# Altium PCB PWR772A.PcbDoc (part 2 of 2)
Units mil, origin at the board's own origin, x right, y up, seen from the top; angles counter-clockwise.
Board outline 3500 x 3300 mil, 4 copper layers (Top Layer, Signal Layer 1, Signal Layer 2, Bottom Layer), stack 30.2 mil thick; 164 components, 50 nets, 349 pads, 587 vias.
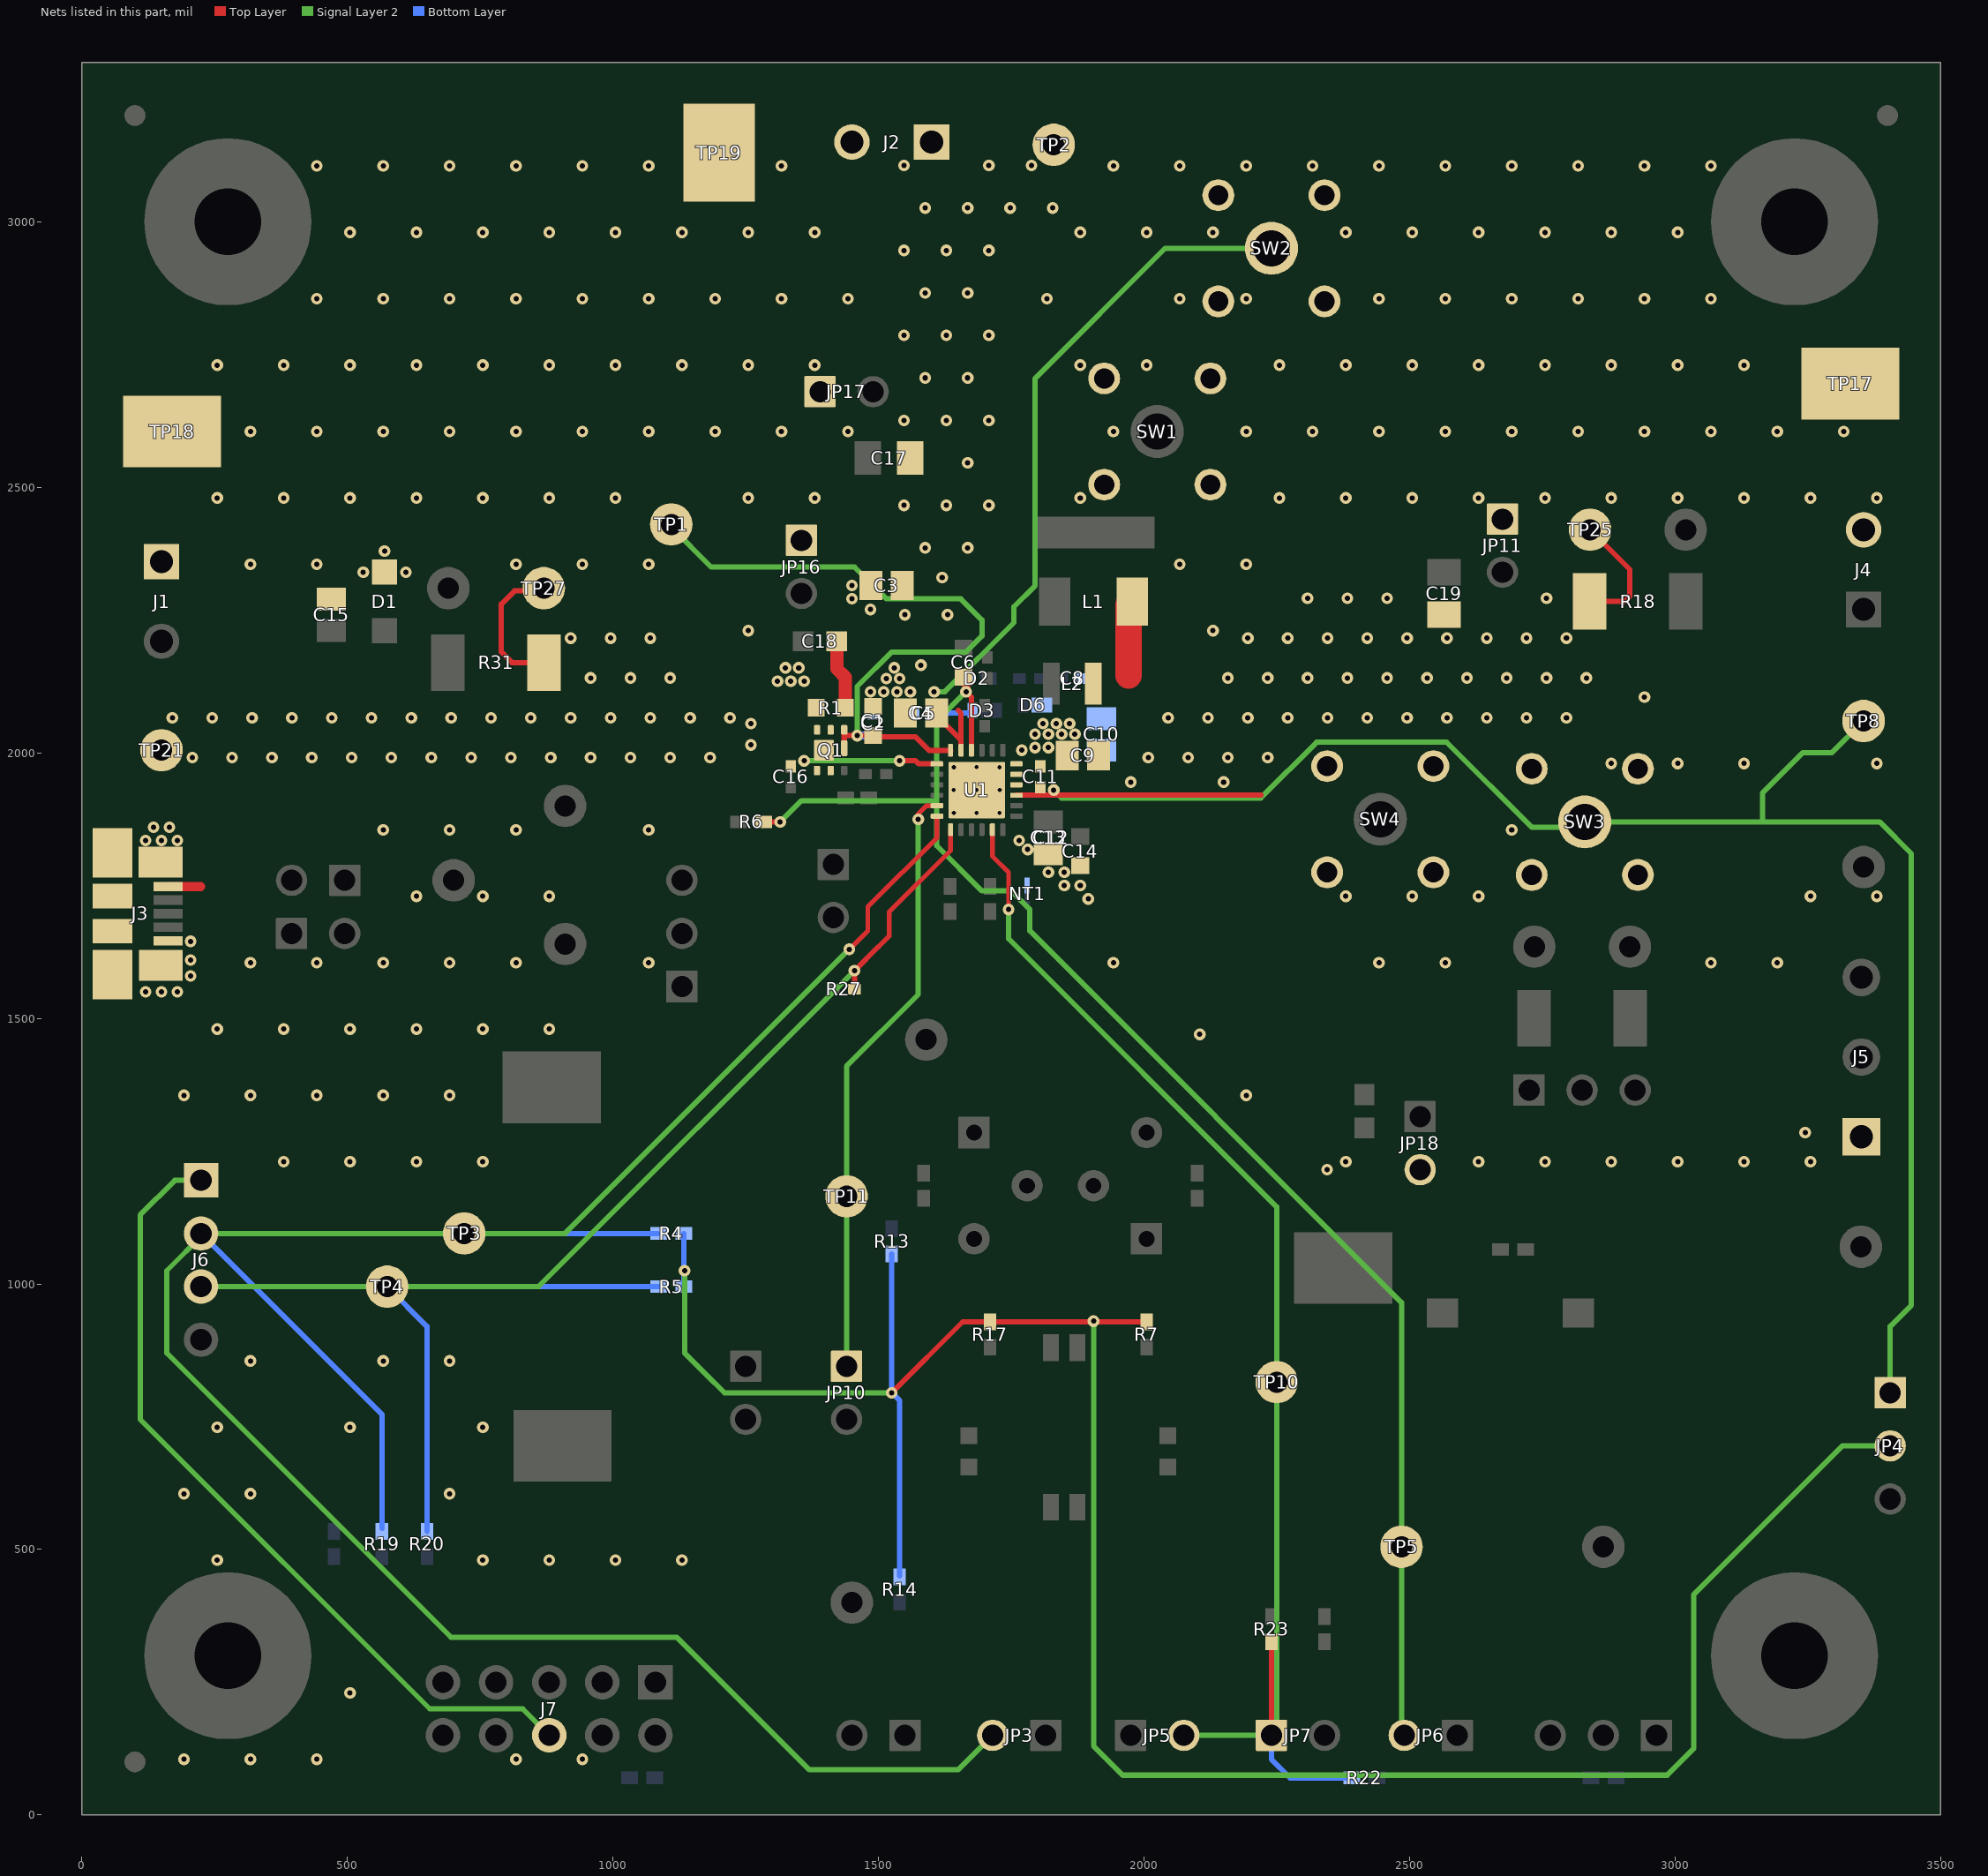
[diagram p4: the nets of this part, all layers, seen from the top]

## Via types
v1: diameter 22, hole 10, Top Layer to Bottom Layer, tented both sides, 573 vias
v2: diameter 19.68, hole 7.87, Top Layer to Bottom Layer, 14 vias

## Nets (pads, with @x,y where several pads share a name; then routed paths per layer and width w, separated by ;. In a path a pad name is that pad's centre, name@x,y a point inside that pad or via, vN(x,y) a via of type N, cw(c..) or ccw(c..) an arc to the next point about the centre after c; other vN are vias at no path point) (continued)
PGND: C1.2 C2.2 C3.2 C4.2 C5.2 C8.2 C9.2 C10.2 C11.2 C12.1 C13.1 C14.1 C15.2 D1.2 D6.2 J1.1 J2.2 J3.5 J3.6 J3.7 J3.8 J3.9 J3.10 J3.11 J4.2 J5.1 J6.1 J7.6 JP11.1 JP16.1 JP17.1 JP18.2 NT1.1 SW1.2 SW1.3 SW1.4 SW1.5 SW2.2 SW2.3 SW2.4 SW2.5 SW3.2 SW3.3 SW3.4 SW3.5 SW4.2 SW4.3 SW4.4 SW4.5 TP17.1 TP18.1 TP19.1 U1.17 U1.18 U1.25@1685,1930 | length 1542.8
  Signal Layer 2 w10: J6.1@224.41,1195 175,1195 110,1130 110,745 655,200 830,200 J7.6@880,150
  other v1: 192.5,105 317.5,105 442.5,105 817.5,105 942.5,105 505,230 255,480 755,480 880,480 1005,480 1130,480 192.5,605 317.5,605 692.5,605 255,730 505,730 755,730 317.5,855 567.5,855 692.5,855 2345,1215 380,1230 505,1230 630,1230 755,1230 2380,1230 2630,1230 2755,1230 2880,1230 3005,1230 3130,1230 3255,1230 3245,1285 192.5,1355 317.5,1355 442.5,1355 567.5,1355 692.5,1355 2192.5,1355 2105,1470 255,1480 380,1480 505,1480 630,1480 755,1480 880,1480 120,1550 150,1550 180,1550 205,1580 317.5,1605 442.5,1605 567.5,1605 692.5,1605 817.5,1605 1067.5,1605 1942.5,1605 2442.5,1605 2567.5,1605 3067.5,1605 3192.5,1605 205,1610 205,1645 1895,1725 630,1730 755,1730 880,1730 2380,1730 2505,1730 2630,1730 3255,1730 3380,1730 1850,1750 1880,1750 1820,1775 1850,1775 1781,1818 120,1835 150,1835 180,1835 1765,1835 567.5,1855 692.5,1855 817.5,1855 1067.5,1855 2692.5,1855 135,1860 165,1860 2880,1980 3005,1980 3130,1980 3380,1980 1770,2005 1795,2010 1820,2010 1795,2035 1820,2035 1845,2035 1870,2035 1810,2055 1835,2055 1860,2055 2942.5,2105 1485,2115 1510,2115 1535,2115 1560,2115 1310,2135 1335,2135 1360,2135 1515,2140 1540,2140 1325,2160 1350,2160 1530,2160 1255,2230 2130,2230 1485,2270 1450,2290 1450,2315 530,2340 610,2340 317.5,2355 442.5,2355 817.5,2355 942.5,2355 1067.5,2355 2067.5,2355 2192.5,2355 570,2380 255,2480 380,2480 505,2480 630,2480 755,2480 880,2480 1005,2480 1255,2480 1380,2480 1880,2480 2255,2480 2380,2480 2505,2480 2630,2480 2755,2480 2880,2480 3005,2480 3130,2480 3255,2480 3380,2480 317.5,2605 442.5,2605 567.5,2605 692.5,2605 817.5,2605 942.5,2605 1067.5,2605 1192.5,2605 1317.5,2605 1442.5,2605 1942.5,2605 2192.5,2605 2317.5,2605 2442.5,2605 2567.5,2605 2692.5,2605 2817.5,2605 2942.5,2605 3067.5,2605 3192.5,2605 3317.5,2605 255,2730 380,2730 505,2730 630,2730 755,2730 880,2730 1005,2730 1130,2730 1255,2730 1380,2730 1880,2730 2005,2730 2255,2730 2380,2730 2505,2730 2630,2730 2755,2730 2880,2730 3005,2730 3130,2730 442.5,2855 567.5,2855 692.5,2855 817.5,2855 942.5,2855 1067.5,2855 1192.5,2855 1317.5,2855 1442.5,2855 1817.5,2855 2067.5,2855 2192.5,2855 2442.5,2855 2567.5,2855 2692.5,2855 2817.5,2855 2942.5,2855 3067.5,2855 505,2980 630,2980 755,2980 880,2980 1005,2980 1130,2980 1255,2980 1380,2980 1880,2980 2005,2980 2130,2980 2380,2980 2505,2980 2630,2980 2755,2980 2880,2980 3005,2980 442.5,3105 567.5,3105 692.5,3105 817.5,3105 942.5,3105 1067.5,3105 1317.5,3105 1942.5,3105 2067.5,3105 2192.5,3105 2317.5,3105 2442.5,3105 2567.5,3105 2692.5,3105 2817.5,3105 2942.5,3105 3067.5,3105
  other v2: 1642,1887 1685,1886.69 1685,1886.69 1728,1887 1641.69,1930 1641.69,1930 1685,1930 1685,1930 1728.31,1930 1728.31,1930 1642,1973 1685,1973.31 1685,1973.31 1728,1973
PMID: C3.1 C4.1 C5.1 C17.1 D3.1 J2.1 SW2.1 TP2.1 U1.23 | length 1453.1
  Top Layer w10: J2.1@1600,3150 J2.1@1604.53,3145.47 ; C4.1@1604.53,2075 1655.47,2024.06 ; 1650,2080 1655.47,2074.53 1655.47,2024.06 ; U1.23@1655.47,2004.8 1655.47,2024.06
  Signal Layer 2 w10: v1(1605,2115) 1625,2115 1755,2245 1755,2275 1795,2315 1795,2705 2040,2950 SW2.1@2240,2950
  Bottom Layer w10: C5.1@1604.68,2075 D3.1@1675,2075
  other v1: 1580,2165 1550,2260 1630,2260 1620,2330 1588,2386 1668,2386 1548,2466 1628,2466 1708,2466 1668,2546 1548,2626 1628,2626 1708,2626 1588,2706 1668,2706 1548,2786 1628,2786 1708,2786 1588,2866 1668,2866 1548,2946 1628,2946 1708,2946 1588,3026 1668,3026 1748,3026 1828,3026 1548,3106 1708,3106 1788,3106
PULL-UP: JP4.2 R4.1 R5.1 R7.2 R13.1 R14.1 R17.2 | length 4607
  Top Layer w10: v1(1525,795) 1658.62,928.62 R7.2@2005,928.62
  Signal Layer 2 w10: 1135,995 v1(1135,1025) 1135,870 1177.5,827.5 ; 1175,830 1210,795 v1(1525,795) ; v1(1905,930) 1905,130 1960,75 2985,75 3035,125 3035,415 3315,695 JP4.2@3405,695
  Bottom Layer w10: R5.1@1133.62,995 R4.1@1133.62,1095 ; R13.1@1525,1056.38 v1(1525,795) 1540,780 R14.1@1540,450
REGN: C6.1 D2.2 JP6.2 R6.2 TP5.1 U1.22 | length 2901.7
  Top Layer w10: R6.2@1283.62,1870 v1(1315,1870) ; C6.1@1660,2142.44 C6.1@1665,2137.44 ; v1@1662.56,2117.44 v1(1665,2115) 1675.16,2104.84 U1.22@1675.16,2004.8
  Top Layer w15: v1(1665,2115) C6.1@1665,2137.44
  Signal Layer 2 w10: v1(1315,1870) 1355,1910 1610,1910 ; v1(1665,2115) 1610,2060 1610,1910 ; JP6.2@2500,155 2485,170 2485,965 1785,1665 1785,1705 1750,1740 1695,1740 1610,1825 1610,1910
  Bottom Layer w10: D2.2@1658.35,2140 1665,2133.35 v1(1665,2115)
SCL_OTG: J6.2 JP3.2 R4.2 R19.1 TP3.1 U1.6 | length 4983.6
  Top Layer w9: v1(1445,1630) 1480,1665 1480,1710 1610.2,1840.2 U1.6@1610.2,1880.79
  Signal Layer 2 w10: J6.2@224.41,1095 910,1095 v1(1445,1630) ; J6.2@230,1095 160,1025 160,870 695,335 1120,335 1370,85 1650,85 JP3.2@1715,150
  Bottom Layer w10: J6.2@224.41,1095 565,754.41 R19.1@565,540 ; TP3.1@720,1095 R4.2@1085,1095
SDA_/PG: J6.3 R5.2 R20.2 R27.1 TP4.1 U1.7 | length 2859.3
  Top Layer w9: 1500,1635 1520,1655 1520,1700 1635.79,1815.79 U1.7@1635.79,1855.2
  Top Layer w10: R27.1@1454.68,1555 v1(1454.68,1589.68) 1500,1635
  Signal Layer 2 w10: J6.3@224.41,995 TP4.1@575,995 860,995 v1(1454.68,1589.68)
  Bottom Layer w10: R20.2@650,533.62 650,920 TP4.1@575,995 R5.2@1086.38,995 R5.2@1090,995
STAT_/IMON: JP10.1 TP11.1 U1.5 | length 1137.5
  Top Layer w9: v1(1575,1875) 1575,1885 1590.47,1900.47 U1.5@1610.2,1900.47
  Signal Layer 2 w10: JP10.1@1440,845 TP11.1@1440,1165 1440,1410 1575,1545 v1(1575,1875)
SYS: C9.1 C10.1 C11.1 C19.1 JP4.1 L1.2 L2.2 R18.1 SW3.1 TP8.1 TP25.1 U1.15 U1.16 | length 3921.1
  Top Layer w10: U1.15@1759.8,1920.16 2220.16,1920.16 ; R18.1@2839.45,2285 2905,2285 2915,2295 2915,2345 TP25.1@2840,2420
  Top Layer w50: 1971.13,2146.13 1971.13,2278.29 L1.2@1977.83,2285
  Signal Layer 2 w10: v1(1830,1930) 1845,1915 2220,1915 2325,2020 2570,2020 2730,1860 SW3.1@2825,1860 ; SW3.1@2830,1870 3165,1870 ; TP8.1@3355,2060 3295,2000 3240,2000 3165,1925 3165,1870 ; JP4.1@3405,795 3405,920 3445,960 3445,1810 3385,1870 3165,1870
  other v1: 1975,1945 2150,1945 2008,1991 2083,1991 2158,1991 2233,1991 2045.5,2066 2120.5,2066 2195.5,2066 2270.5,2066 2345.5,2066 2420.5,2066 2495.5,2066 2570.5,2066 2645.5,2066 2720.5,2066 2795.5,2066 2158,2141 2233,2141 2308,2141 2383,2141 2458,2141 2533,2141 2608,2141 2683,2141 2758,2141 2833,2141 2195.5,2216 2270.5,2216 2345.5,2216 2420.5,2216 2495.5,2216 2570.5,2216 2645.5,2216 2720.5,2216 2795.5,2216 2308,2291 2383,2291 2458,2291 2758,2291
TS: JP5.2 JP7.1 R22.1 R23.2 TP10.1 U1.11 | length 2473.4
  Top Layer w9: U1.11@1714.53,1855.2 1714.53,1805.47 1745,1775 1745,1710 v1@1750,1705
  Top Layer w10: JP7.1@2240,150 R23.2@2240,326.38
  Signal Layer 2 w10: v1@1750,1705 1745,1700 1745,1650 2250,1145 2250,875 JP7.1@2250,160 ; JP5.2@2075,150 JP7.1@2240,150
  Bottom Layer w10: JP7.1@2240,150 2240,105 2275,70 R22.1@2391.38,70
  other v1: 1745,1705
VAC: C16.1 J3.1 Q1.1 Q1.2 Q1.5 Q1.6 Q1.8 R1.1 R31.2 TP21.1 TP27.1 U1.1 | length 587.6
  Top Layer w10: TP27.1@870,2305 815,2305 790,2280 790,2190 810,2170 R31.2@870.55,2170 ; R1.1@1382.44,2085 R1.1@1384.41,2083.03 ; v1@1540,1990 1545,1985 1570,1985 1575.79,1979.21 U1.1@1610.2,1979.21
  Top Layer w17: J3.1@162.36,1748.31 223.31,1748.31
  Signal Layer 2 w10: v1(1360,1985) v1(1540,1985)
  other v1: 208,1991 283,1991 358,1991 433,1991 508,1991 583,1991 658,1991 733,1991 808,1991 883,1991 958,1991 1033,1991 1108,1991 1183,1991 1260,2015 1260,2055 170.5,2066 245.5,2066 320.5,2066 395.5,2066 470.5,2066 545.5,2066 620.5,2066 695.5,2066 770.5,2066 845.5,2066 920.5,2066 995.5,2066 1070.5,2066 1145.5,2066 1220.5,2066 958,2141 1033,2141 1108,2141 920.5,2216 995.5,2216 1070.5,2216
VBUS: C1.1 C2.1 C18.1 Q1.4 Q1.7 R1.2 TP1.1 U1.24 | length 1494.5
  Top Layer w10: 1435.59,2030 1438.03,2032.44 v1(1460,2032.44) C1.1@1490,2032.44 1492.44,2030 1570,2030 1595.2,2004.8 U1.24@1635.79,2004.8
  Top Layer w11: Q1.7@1435.59,2008.74 1435.59,2030 Q1.4@1435.59,2043.39
  Top Layer w25: C18.1@1421.5,2210 1421.5,2158.5 1437.56,2142.44 R1.2@1437.56,2085
  Signal Layer 2 w10: TP1.1@1110,2455 1110,2425 1185,2350 1455,2350 1515,2290 1655,2290 1695,2250 1695,2220 1665,2190 1525,2190 1460,2125 v1(1460,2032.44)
  Bottom Layer w10: C2.1@1487.13,2032.44 C2.1@1490,2035.32
  Bottom Layer w15: v1(1460,2032.44) C2.1@1487.13,2032.44
pads on no net: FID1.1 FID2.1 FID3.1 FID4.1 FID5.1 FID6.1 H1.1 H2.1 H3.1 H4.1 H5.0 H6.0 H7.0 H8.0 J3.4 J7.1 J7.3 J7.4 J7.5 J7.7 J7.8 LBL1.0 Q1.0 SH-JP1.0 SH-JP2.0 SH-JP3.0 SH-JP4.0 SH-JP5.0 SH-JP6.0 SH-JP7.0 SH-JP8.0 SH-JP9.0 SH-JP10.0 SH-JP11.0 SH-JP12.0 SH-JP13.0 SH-JP14.0 SH-JP15.0 SH-JP16.0 SH-JP17.0 SH-JP18.0 U1.25@1657.64,1902.64 U1.25@1657.64,1957.36 U1.25@1712.36,1902.64 U1.25@1712.36,1957.36

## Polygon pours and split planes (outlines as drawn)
PGND on Top Layer "Top Layer-No Net" (solid, remove dead copper, pour order 56): 770,1231.61 770,584.44 1155,584.44 1155,50 50,50 50,1231.61
PGND on Top Layer "Top Layer-No Net" (solid, remove dead copper, pour order 58): 50,1150 3175,1150 3450,1150 3450,3250 50,3250
AGND on Top Layer "Top Layer-No Net" (solid, remove dead copper, pour order 57): 785,1455 995,1455 1080,1540 1130,1590 1170,1590 1500,1590 1605,1695 1765,1695 1765,1715 1785,1735 1810,1735 1810,1670 1840,1640 2340,1140 2630,1140 3450,1140 3450,50 1170,50 1170,605 785,605
VAC on Top Layer "Top Layer-No Net" (solid, remove dead copper, pour order 53): 420,2095 840,2095 840,2255 1070,2255 1080,2255 1280,2055 1350,2055 1415,2055 1415,1990 1415,1960 1295,1960 420,1960
VBUS on Top Layer "Top Layer-No Net" (solid, remove dead copper, pour order 51): 1635,1995 1580,1995 1575,2000 1570,2005 1555,2005 1530,2005 1525,2000 1515,1990 1430,1990 1430,2055 1475,2055 1515,2055 1530,2040 1535,2040 1610,2040 1635,2015
PMID on Top Layer "Top Layer-No Net" (solid, remove dead copper, pour order 52): 1660,2005 1660,2055 1660,2090 1650,2100 1630,2120 1630,2135 1630,2225 1665,2260 1760,2355 1760,2400 1760,3190 1525,3190 1525,2220 1525,2175 1555,2145 1585,2115 1585,2055 1590,2050
NetC7_1 on Top Layer "Top Layer-No Net" (solid, remove dead copper, pour order 50): 1730,2160 1730,2125 1730,2040 1720,2030 1710,2020 1710,2015 1710,1995 1740,1995 1740,2010 1750,2020 1840,2095 1845,2155
SYS on Top Layer "Top Layer-No Net" (solid, remove dead copper, pour order 55): 1750,1945 1820,1945 1835,1960 1885,1960 1890,1965 1890,2050 1875,2065 1875,2075 1875,2165 1905,2165 1935,2165 1960,2165 2112.5,2165 2292.5,2345 2475,2345 2870,2345 2870,2100 2870,2010 2325,2010 2285,1970 2230,1915 1750,1915
BAT on Top Layer "Top Layer-No Net" (solid, remove dead copper, pour order 54): 1750,1905 1925,1905 2100,1905 2250,1755 2435,1570 3015,1570 2765,1570 2765,1415 2680,1415 2680,1335 2355,1335 2320,1335 1960,1695 1910,1745 1910,1810 1895,1825 1865,1825 1845,1845 1780,1845 1750,1875
PGND on Bottom Layer "Top Layer-No Net" (solid, remove dead copper, pour order 68): 50,1150 3175,1150 3450,1150 3450,1275 3450,3250 50,3250
AGND on Bottom Layer "Top Layer-No Net" (solid, remove dead copper, pour order 67): 785,1245 995,1455 1080,1540 1130,1590 1170,1590 1500,1590 1605,1695 1765,1695 1765,1735 1790,1735 1810,1735 1810,1670 1840,1640 2340,1140 2630,1140 3450,1140 3450,50 1140,50 1140,605 785,605
PMID on Bottom Layer "Top Layer-No Net" (solid, remove dead copper, pour order 63): 1630,2065 1630,2100 1630,2120 1630,2135 1630,2225 1665,2260 1725,2320 1725,2395 1725,3190 1525,3190 1525,2205 1570,2160 1585,2145 1585,2115 1585,2065 1615,2065
VAC on Bottom Layer "Top Layer-No Net" (solid, remove dead copper, pour order 64): 895,2255 955,2255 1020,2255 1150,2255 1252.5,2152.5 1350,2055 1415,2055 1415,1990 1415,1960 1295,1960 105,1960 105,2095 895,2095
SYS on Bottom Layer "Top Layer-No Net" (solid, remove dead copper, pour order 66): 1815,1960 1850,1995 1885,2030 1900,2030 1910,2030 1977.5,2030 2018.75,2071.25 2080,2132.5 2292.5,2345 2475,2345 2870,2345 2870,2100 2870,2010 2325,2010 2285,1970 2230,1915 1815,1915
BAT on Bottom Layer "Top Layer-No Net" (solid, remove dead copper, pour order 65): 1815,1905 1925,1905 2100,1905 2250,1755 2435,1570 2755,1570 2755,1410 2680,1410 2680,1335 2355,1335 2320,1335 1960,1695 1910,1745 1910,1805 1895,1820 1870,1845 1815,1845
VAC on Signal Layer 2 "Top Layer-No Net" (solid, remove dead copper, pour order 60): 840,2255 1150,2255 1165,2240 1280,2125 1280,2105 1280,1960 840,1960 105,1960 105,2090 840,2090
BAT on Signal Layer 2 "Top Layer-No Net" (solid, remove dead copper, pour order 61): 1910,1855 2125,1855 2150,1855 2325,1680 2435,1570 3015,1570 3020,1570 2735,1570 2755,1560 2755,1420 2675,1415 2675,1335 2320,1335 2280,1375 1910,1745 1845,1810 1845,1815 1845,1880 1865,1880 1865,1855
SYS on Signal Layer 2 "Top Layer-No Net" (solid, remove dead copper, pour order 62): 1845,1930 2195,1930 2205,1930 2325,2050 2435,2050 2575,2050 2615,2010 2870,2010 2870,2100 2870,2345 2475,2345 2290,2345 1945,2000 1850,2000 1815,1965 1815,1915 1830,1915
PGND on Signal Layer 1 "Top Layer-No Net" (solid, remove dead copper, pour order 59): 50,50 3450,50 3450,3250 50,3250

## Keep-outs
Keep-Out Layer:
  lines w10: -5,0 ccw(c0,0) 0,-5 ; -5,0 ccw(c0,0) 0,-5 ; -5,0 -5,3300 ; -5,3300 cw(c0,3300) 0,3305 ; -5,3300 cw(c0,3300) 0,3305 ; 0,-5 3500,-5 ; 0,3305 3500,3305 ; 3500,-5 ccw(c3500,0) 3505,0 ; 3500,-5 ccw(c3500,0) 3505,0 ; 3500,3305 cw(c3500,3300) 3505,3300 ; 3500,3305 cw(c3500,3300) 3505,3300 ; 3505,0 3505,3300
  text ".Layer_Name" at 577,-858.49 h60

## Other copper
Top Layer:
  rectangle net NetJ5_2: 3280,1330 3400,1530
  rectangle net NetJ5_2: 2965,1330 3305,1575
  rectangle net NetJ4_1: 2990,2115 3400,2345
  rectangle net VAC: 105,1890 440,2092.76
  rectangle net NetC15_1: 105,2105 720,2255
  rectangle net PMID: 1695,3010 1875,3190
  rectangle net VBUS: 1430,2050 1455,2100
  rectangle net VAC: 210,1740 305,1900
  region net VAC: 305,1740 526.78,1961.78 441.78,2046.78 220,1825
  rectangle net VAC: 1365,2045 1400,2085
  rectangle net NetJ5_2: 2880,1405 2975,1575
  pour cut-out: 1870,2360 1957.5,2360 2019.36,2342.28 2025,2175 1870,2175
  pour cut-out: 1830,2075 1870,2075 1870,2080 1835,2080
  text ".Layer_Name" at 577,-858.49 h60
Signal Layer 1:
  text ".Layer_Name" at 577,-858.49 h60
Signal Layer 2:
  rectangle net NetC15_1: 105,2105 650,2255
  rectangle net NetJ4_1: 2990,2115 3400,2345
  rectangle net NetJ5_2: 3280,1390 3400,1530
  rectangle net NetJ5_2: 2965,1365 3300,1575
  rectangle net PMID: 1705,3010 1875,3190
  rectangle net PMID: 1530,2305 1760,3190
  text ".Layer_Name" at 577,-858.49 h60
Bottom Layer:
  rectangle net NetJ4_1: 2990,2115 3400,2345
  rectangle net NetJ5_2: 3280,1330 3400,1530
  rectangle net NetJ5_2: 2965,1330 3305,1575
  rectangle net PMID: 1700,3010 1875,3190
  text ".Layer_Name" at 577,-858.49 h60

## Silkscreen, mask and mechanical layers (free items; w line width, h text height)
Top Overlay:
  region: 1290,2830 990,2830 990,2730 1290,2730
  text "GND" at 980,3065 h60
  text "PMID" at 1770,3030 h60
  text "GND" at 1390,2930 h60
  text "PMID" at 1560,2930 h60
  text "'.PRJ_Number'.PCB_Rev-" at 450,2745 h108.27
  text "GND" at 3065,2640 h60
  text "GND" at 300,2535 h60
  text "GND" at 3090,2395 h60
  text "GND" at 310,2345 h60
  text "VBUS" at 1035,2275 h60
  text "SYS" at 3090,2255 h60
  text "VAC" at 310,2180 h60
  text "SYS" at 3160,2045 h60
  text "VAC" at 230,1960 h60
  text "BATSNS" at 3070,1795 h60
  text "ACDRV" at 820,1790 h60
  text "ICHG" at 3105,1750 h60
  text "REGN" at 1194,1744 h55
  text "D-_PG" at 630,1650 h60
  text "PSEL" at 1194,1644 h60
  text "BATSNS" at 2975,1560 h60
  text "GND" at 1195,1540 h60
  text "D+_PSEL" at 780,1530 h60
  text "BAT" at 2325,1515 h60
  text "BAT" at 3065,1410 h60
  text "ILIM" at 1540,1350 h60
  text "GND" at 635,1315 h60
  text "GND" at 3060,1260 h60
  text "BATSNS" at 2725,1220 h60
  text "GND" at 279,1174 h60
  text "GND" at 2320,1120 h60
  text "SCL" at 279,1074 h60
  text "STAT /IMON" at 1300,1055 h60
  text "BAT" at 3160,1030 h60
  text "SCL" at 804,1029 h60
  text "SDA" at 279,974 h60
  text "SDA" at 644,924 h60
  text "/CE" at 279,874 h60
  text "/QON" at 2630,805 h60
  text "SYS" at 3204,774 h60
  text "TS" at 2355,745 h60
  text "PULL-UP" at 3145,680 h50
  text "GND" at 665,655 h60
  text "BAT" at 3194,579 h60
  text "PG" at 2005,565 h60
  text "STAT" at 1600,560 h60
  text "REGN" at 2410,395 h60
  text "/QON_VSET" at 2710,395 h60
  text "/CE" at 1290,360 h60
  text "/CE" at 1380,40 h60
  text "GND" at 1500,40 h60
  text "OTG" at 1650,40 h60
  text "GND" at 1780,40 h60
  text "GND" at 1920,40 h60
  text "TS" at 2050,40 h60
  text "TS 10K" at 2205,40 h60
  text "RTOP TS" at 2430,40 h60
  text "VSET" at 2795,40 h60
  text ".Layer_Name" at 577,-858.49 h60
Bottom Overlay:
  text ".Layer_Name" at 577,-858.49 h60
Top Paste:
  text ".Layer_Name" at 577,-858.49 h60
Bottom Paste:
  text ".Layer_Name" at 577,-858.49 h60
Top Solder:
  text ".Layer_Name" at 577,-858.49 h60
  text ".Layer_Name" at 577,-858.49 h60
Bottom Solder:
  text ".Layer_Name" at 577,-858.49 h60
Drill Guide:
  text ".Layer_Name" at 577,-858.49 h60
M1 Board Outline:
  the board outline again, w10
  text ".Layer_Name" at 577,-858.49 h60
M2 Board Dimensions:
  rectangle: 0,-275 125,-150
  rectangle: 125,-400 500,-275
  lines w7: 0,-275 1000,-275 ; 125,-400 125,-150 ; 250,-400 250,-150 ; 500,-400 500,-150 ; 750,-400 750,-150 ; 0,-400 1000,-400 1000,-150 0,-150 0,-400
  text ".Layer_Name" at 577,-858.49 h60
M3 3D STEP Top:
  text ".Layer_Name" at 577,-858.49 h60
M4 3D STEP Bottom:
  text ".Layer_Name" at 577,-858.49 h60
M5 Assembly Top:
  lines w5: 1080,1710 1180,1710 ; 2815,100 2815,200 ; 2875,1315 2875,1415 ; 3355,645 3455,645
  lines w10: -292,-930.17 6308,-930.17 ; -292,-726.83 6310,-726.83 ; -292,-523.5 -292,-1133.5 3713,-1133.5 6310,-1133.5 6310,-523.5 -291.5,-523.5 -291.5,-1133.5 1284,-1133.5 ; 2173,-1133.5 2173,-523.5 ; 3440,-726.83 3440,-523.5 ; 4280,-726.83 4280,-523.5 ; 4902,-1140 4902,-937.17
  text "SH-JP17" at 1340,2750 h60
  text "SH-JP11" at 2770,2280 h60 r90
  text "SH-JP16" at 1280,2240 h60 r90
  text "SH-JP14" at 340,1830 h60
  text "SH-JP15" at 1340,1620 h60 r90
  text "SH-JP13" at 340,1540 h60
  text "SH-JP1" at 1065,1515 h60 r90
  text "SH-JP8" at 2680,1250 h60
  text "SH-JP18" at 2630,1160 h60 r90
  text "SH-JP12" at 1180,690 h60 r90
  text "SH-JP10" at 1550,680 h60 r90
  text "SH-JP4" at 3330,640 h60 r90
  text "SH-JP3" at 1670,40 h60
  text "SH-JP6" at 2450,40 h60
  text "SH-JP9" at 2820,40 h60
  text "SH-JP2" at 1410,30 h60
  text "SH-JP5" at 1930,30 h60
  text "SH-JP7" at 2190,30 h60
  text "COMPONENTS MARKED 'DNP' SHOULD NOT BE POPULATED." at 1153.5,-318.5 h60
  text "ASSEMBLY VARIANT:" at 1153,-434 h60
  text ".VariantName" at 2189,-434 h60
  text "PCB VIEWED FROM TOP SIDE" at -228.5,-655.67 h60
  text "BOARD #:" at 2248,-655.67 h60
  text ".PRJ_Number" at 2793.5,-655.67 h60
  text "REV:" at 3638,-655.67 h60
  text ".PCB_Rev" at 3929.5,-655.67 h60
  text "SVN REV:" at 4476,-655.67 h60
  text ".VersionControl_RevNumber" at 4982,-655.67 h60
  text "TID #:" at 2248,-859 h60
  text ".TID" at 2793.5,-859 h60
  text "PLOT NAME =" at -228.5,-1064.34 h60
  text ".plot_File_Name" at 577,-1064.34 h60
  text "GENERATED    :" at 2250,-1064.34 h60
  text ".Print_Date" at 3119.5,-1064.34 h60
  text ".Print_Time" at 3848.5,-1064.34 h60
  text "TEXAS INSTRUMENTS" at 5113,-1064.34 h60
M6 Assembly Bottom:
  lines w10: -292.5,-727.33 6309.5,-727.33 ; -290.5,-930.67 6309.5,-930.67 ; 1115.5,-1140.5 1115.5,-937.67 ; 1737.5,-727.33 1737.5,-524 ; 2577.5,-727.33 2577.5,-524 ; 3844.5,-1134 3844.5,-524 ; 4733.5,-1134 6309,-1134 6309,-524 -292.5,-524 -292.5,-1134 2304.5,-1134 6309.5,-1134 6309.5,-524
  text "COMPONENTS MARKED 'DNP' SHOULD NOT BE POPULATED." at 6102,-318 h60
  text ".VariantName" at 5058,-434 h60
  text "ASSEMBLY VARIANT:" at 6097,-434 h60
  text ".VersionControl_RevNumber" at 1035.5,-656.17 h60
  text "SVN REV:" at 1541.5,-656.17 h60
  text ".PCB_Rev" at 2088,-656.17 h60
  text "REV:" at 2379.5,-656.17 h60
  text ".PRJ_Number" at 3224,-656.17 h60
  text "BOARD #:" at 3769.5,-656.17 h60
  text "PCB VIEWED FROM BOTTOM SIDE" at 6246,-656.17 h60
  text ".TID" at 3224,-859.5 h60
  text "TID #:" at 3769.5,-859.5 h60
  text "TEXAS INSTRUMENTS" at 904.5,-1064.84 h60
  text ".Print_Time" at 2169,-1064.84 h60
  text ".Print_Date" at 2898,-1064.84 h60
  text "GENERATED    :" at 3767.5,-1064.84 h60
  text ".plot_File_Name" at 5440.5,-1064.84 h60
  text "PLOT NAME =" at 6246,-1064.84 h60
M9 Title Sheet:
  drawing of 57 lines, arcs and shapes, not listed
  text "1" at 739.84,8036.5 h70
  text "2" at 3235.5,8036.5 h70
  text "3" at 5724.84,8036.5 h70
  text "4" at 8231.51,8036.5 h70
  text "5" at 10730.5,8036.5 h70
  text "6" at 13235.5,8036.5 h70
  text "A" at -416.5,6893.5 h70
  text "A" at 14383.5,6893.5 h70
  text "B" at -416.5,4513.5 h70
  text "B" at 14383.5,4513.5 h70
  text "C" at -416.5,2138.5 h70
  text "C" at 14383.5,2138.5 h70
  text "PROJECT TITLE:" at 11343.5,277.5 h45
  text ".PRJ_Title" at 11393.5,144.17 h70
  text "DESIGNED FOR:" at 11343.5,-23.5 h45
  text ".PRJ_Customer" at 11393.5,-163.5 h70
  text "D" at -416.5,-231.5 h70
  text "D" at 14383.5,-231.5 h70
  text "FILE NAME:" at 11343.5,-323.5 h45
  text ".PCB_File_Name_No_Path" at 11393.5,-443.5 h70
  text "Texas Instruments (TI) and/or its licensors do not warrant the accuracy or completeness of this specification" at 6374,-605.34 h45
  text "ENGINEER:" at 11343.5,-613.5 h45
  text "LAYOUT BY:" at 12848.5,-613.5 h45
  text "or any information contained therein. TI and/or its licensors do not warrant that this design will meet" at 6329.01,-718 h45
  text ".PRJ_Engineer" at 11393.5,-768.49 h70
  text ".PCB_Layout" at 12899,-768.49 h70
  text "the specifications, will be suitable for your application or fit for any particular purpose, or will operate in" at 6329.01,-830.67 h45
  text ".Layer_Name" at 577,-858.49 h60
  text "ALTIUM DESIGNER VERSION:" at 12848.5,-923.5 h45
  text "an implementation. TI and/or its licensors do not warrant that the design is production worthy. You should" at 6329.01,-943.33 h45
  text "completely validate and test your design implementation to confirm the system functionality for your application." at 6374,-1056 h45
  text ".print_Scale" at 11393.5,-1056.83 h70
  text ".Application_BuildNumber" at 12899,-1056.83 h70
  text "1" at 739.84,-1263.5 h70
  text "2" at 3235.5,-1263.5 h70
  text "3" at 5724.84,-1263.5 h70
  text "4" at 8231.51,-1263.5 h70
  text "5" at 10730.5,-1263.5 h70
  text "6" at 13235.5,-1263.5 h70
M10 Fab Notes:
  drawing of 173 lines, arcs and shapes, not listed
  text "DESIGN INFORMATION" at 12378.02,6201 h60
  text "MIN. TRACK WIDTH:" at 11733.46,6021 h60
  text "8" at 12829.7,6021 h60
  text "MIL" at 12984.46,6021 h60
  text "MIN. CLEARANCE:" at 11733.46,5889 h60
  text "5" at 12769.7,5889 h60
  text "MIL" at 12984.46,5889 h60
  text "MIN. VIA PAD SIZE:" at 11733.46,5757 h60
  text "20" at 12799.71,5757 h60
  text "MIL" at 12984.46,5757 h60
  text "0.05mm (2MIL)" at 12428.46,5615.29 h60
  text "MINIMUM ANNULAR RING" at 11404.23,5611 h60
  text "EXTERNAL" at 13136.46,5611 h60
  text "PER" at 11604.23,5493 h60
  text "IPC-D-275 CLASS 2 LEVEL C" at 11824.23,5493 h60
  text "MIL, HOLES" at 13312.46,5380.71 h60
  text "+/-" at 12920,5380 h60
  text "+/-" at 13774,5380 h60
  text "REGISTRATION TOLERANCES:" at 11404.23,5375 h60
  text "METAL" at 12604,5375 h60
  text "5" at 13180.2,5375 h60
  text "3" at 14013.2,5375 h60
  text "MIL" at 14129.46,5375 h60
  text "+/-" at 13774,5262 h60
  text "HOLE SIZE TOLERANCE (UNLESS OTHERWISE SPECIFIED):" at 11404.23,5257 h60
  text "3" at 14013.2,5257 h60
  text "MIL" at 14129.46,5257 h60
  text "MATERIAL:" at 11329.46,5047.54 h60
  text "FR-4 High Tg" at 12315.9,4907.21 h60
  text "FR-408" at 11750.46,4898.64 h60
  text "OTHER" at 13238.46,4898.64 h60
  text "X" at 12161,4895 h60
  text "62 MIL (1.6mm) +/-10%" at 12070.56,4735.92 h60
  text "THICKNESS:" at 11404.23,4731.64 h60
  text "OTHER" at 13355.46,4731.64 h60
  text "31 MIL+/-10%" at 13640.56,4730.92 h60
  text "X" at 13230,4730 h60
  text "TOLERANCE:" at 11404.23,4573.64 h60
  text "X" at 12243.53,4573.64 h60
  text "ANSI IPC-6012 TYPE 3 CLASS 2" at 12430.48,4573.64 h60
  text "OTHER +/-" at 12430.46,4417.64 h60
  text "BOW & TWIST:" at 11404.23,4260.64 h60
  text "X" at 12243.53,4260.64 h60
  text "ANSI IPC-6012 TYPE 3 CLASS 2" at 12430.48,4260.64 h60
  text "OTHER +/-" at 12430.46,4102.13 h60
  text "DRILLING:" at 11329.46,3963.64 h60
  text "REFERENCE:" at 11404.23,3846.64 h60
  text "X" at 12052.46,3846.64 h60
  text "AS SHOWN" at 12239.46,3846.64 h60
  text "X" at 12953.46,3846.64 h60
  text "NC_DRILL FILES" at 13090.46,3846.64 h60
  text "PTH MIN COPPER THICKNESS:" at 11404.23,3688.64 h60
  text "X" at 12754.46,3688.64 h60
  text "1MIL" at 12891.46,3688.64 h60
  text "OTHER" at 13388.46,3688.64 h60
  text "BOARD FINISH:" at 11329.46,3529.64 h60
  text "SILKSCREEN:" at 11484.68,3411.64 h60
  text "X" at 12433.46,3411.64 h60
  text "TOP" at 12559.46,3411.64 h60
  text "X" at 12943.46,3411.64 h60
  text "BOTTOM" at 13070.46,3411.64 h60
  text "SILKSCREEN COLOR:" at 11484.68,3244.64 h60
  text "X" at 12432.42,3244.64 h60
  text "WHITE" at 12559.46,3244.64 h60
  text "OTHER" at 13070.46,3244.64 h60
  text "X" at 12563.42,3085.44 h60
  text "GREEN" at 12690.46,3085.44 h60
  text "OTHER" at 13308.46,3085.44 h60
  text "SOLDER RESIST COLOR:" at 11484.68,3074.64 h60
  text "X" at 12563.42,2915.44 h60
  text "MATTE" at 12690.46,2915.44 h60
  text "SEMI-GLOSS" at 13308,2914.8 h60
  text "IMMERSION GOLD (ENIG)" at 12390.46,2726.92 h60
  text "ENEPIG" at 13728,2723.64 h60
  text "SURFACE FINISH:" at 11329.46,2722.64 h60
  text "X" at 12203.51,2722.64 h60
  text "IMM. TIN/SILVER OR EQUIV" at 11659,2565.64 h60
  text "OTHER" at 13090.46,2565.64 h60
  text "ARRAY/PANEL:" at 11329.46,2386.64 h60
  text "CUT AND TRIM PER M1 BOARD OUTLINE" at 12390.46,2382.35 h60
  text "N.C. ROUTE" at 12390.46,2230.64 h60
  text "X" at 13069.46,2230.64 h60
  text "V. SCORE" at 13256.46,2230.64 h60
  text "CERTIFICATION:" at 11329.46,2093.64 h60
  text "MATERIALS AND WORKMANSHIP FOR ALL PCBS" at 12054.46,2093.64 h60
  text "TO MEET OR EXCEED THE REQUIREMENTS OF:" at 12054.46,1995.64 h60
  text "X" at 11680.96,1859.13 h60
  text "ANSI IPC-A-600F CLASS ->" at 11819.96,1859.13 h60
  text "X" at 13459.02,1859.13 h60
  text "2" at 13577.96,1859.14 h60
  text "1" at 13262.96,1857.64 h60
  text "3" at 13931.96,1857.64 h60
  text "X" at 12495.02,1699.64 h60
  text "RoHS" at 12631.96,1699.64 h60
  text "OTHER" at 13276.36,1699.64 h60
  text "PER ORDER" at 13673.42,1699.64 h60
  text "ALL BOARDS MUST MEET OR EXCEED UL94-V0 REQUIREMENTS." at 11357,1534 h60
  text "PCB MUST BEAR THE UL94V-0 UL REGISTERED MATERIAL ID NUMBER" at 11357,1414 h60
  text "ADDITIONAL REQUIREMENTS:" at 11329.46,1240.64 h60
  text "MICROSECTION:" at 11404.23,1125.64 h60
  text "YES" at 12309.96,1125.64 h60
  text "REQUIRED" at 13171.46,969.49 h60
  text "BARE BOARD ELEC. TEST:" at 11404.23,966.64 h60
  text "NONE" at 12709.96,966.64 h60
  text "X" at 13044.46,966.64 h60
  text "PER ORDER" at 13763.46,966.64 h60
  text ".Layer_Name" at 577,-858.49 h60
M11 Gerber Information:
  lines w10: -292,-930.17 6308,-930.17 ; -292,-726.83 6310,-726.83 ; -292,-523.5 -292,-1133.5 3713,-1133.5 6310,-1133.5 6310,-523.5 -291.5,-523.5 -291.5,-1133.5 1284,-1133.5 ; 2173,-1133.5 2173,-523.5 ; 3440,-726.83 3440,-523.5 ; 4280,-726.83 4280,-523.5 ; 4902,-1140 4902,-937.17
  text "ALL ARTWORK VIEWED FROM TOP SIDE" at -228.5,-655.67 h60
  text "BOARD #:" at 2248,-655.67 h60
  text ".PRJ_Number" at 2793.5,-655.67 h60
  text "REV:" at 3638,-655.67 h60
  text ".PCB_Rev" at 3929.5,-655.67 h60
  text "SVN REV:" at 4476,-655.67 h60
  text ".VersionControl_RevNumber" at 4982,-655.67 h60
  text "LAYER NAME =" at -228.5,-858.49 h60
  text "TID #:" at 2248,-859 h60
  text ".TID" at 2793.5,-859 h60
  text "PLOT NAME =" at -228.5,-1064.34 h60
  text ".plot_File_Name" at 577,-1064.34 h60
  text "GENERATED    :" at 2250,-1064.34 h60
  text ".Print_Date" at 3119.5,-1064.34 h60
  text ".Print_Time" at 3848.5,-1064.34 h60
  text "TEXAS INSTRUMENTS" at 5113,-1064.34 h60
M12 Stackup:
  drawing of 295 lines, arcs and shapes, not listed
  text "Layer" at 9702.5,7767.5 h60
  text "Name" at 10112.41,7767.5 h60
  text "Material" at 11052.15,7767.5 h60
  text "Thickness" at 11911.92,7767.5 h60
  text "Constant" at 12561.76,7767.5 h60
  text "Board Layer Stack" at 13131.62,7767.5 h60
  text "1" at 9702.5,7647.5 h60
  text "Top Overlay" at 10112.41,7647.5 h60
  text "2" at 9702.5,7527.5 h60
  text "Top Solder" at 10112.41,7527.5 h60
  text "Solder Resist" at 11052.15,7527.5 h60
  text "0.40mil" at 11911.92,7527.5 h60
  text "3.5" at 12561.76,7527.5 h60
  text "3" at 9702.5,7407.5 h60
  text "Top Layer" at 10112.41,7407.5 h60
  text "Copper" at 11052.15,7407.5 h60
  text "1.40mil" at 11911.92,7407.5 h60
  text "4" at 9702.5,7287.5 h60
  text "Dielectric1" at 10112.41,7287.5 h60
  text "FR-4 High TG" at 11052.15,7287.5 h60
  text "8.20mil" at 11911.92,7287.5 h60
  text "4.8" at 12561.76,7287.5 h60
  text "5" at 9702.5,7167.5 h60
  text "Signal Layer 1" at 10112.41,7167.5 h60
  text "Copper" at 11052.15,7167.5 h60
  text "1.40mil" at 11911.92,7167.5 h60
  text "6" at 9702.5,7047.5 h60
  text "Dielectric 2" at 10112.41,7047.5 h60
  text "FR-4 High TG" at 11052.15,7047.5 h60
  text "8.20mil" at 11911.92,7047.5 h60
  text "4.8" at 12561.76,7047.5 h60
  text "7" at 9702.5,6927.5 h60
  text "Signal Layer 2" at 10112.41,6927.5 h60
  text "Copper" at 11052.15,6927.5 h60
  text "1.40mil" at 11911.92,6927.5 h60
  text "8" at 9702.5,6807.5 h60
  text "Dielectric 3" at 10112.41,6807.5 h60
  text "FR-4 High TG" at 11052.15,6807.5 h60
  text "8.20mil" at 11911.92,6807.5 h60
  text "4.8" at 12561.76,6807.5 h60
  text "9" at 9702.5,6687.5 h60
  text "Bottom Layer" at 10112.41,6687.5 h60
  text "Copper" at 11052.15,6687.5 h60
  text "1.40mil" at 11911.92,6687.5 h60
  text "10" at 9702.5,6567.5 h60
  text "Bottom Solder" at 10112.41,6567.5 h60
  text "Solder Resist" at 11052.15,6567.5 h60
  text "0.40mil" at 11911.92,6567.5 h60
  text "3.5" at 12561.76,6567.5 h60
  text "11" at 9702.5,6447.5 h60
  text "Bottom Overlay" at 10112.41,6447.5 h60
  text ".Layer_Name" at 577,-858.49 h60
M13 Component Bodies Top:
  text ".Layer_Name" at 577,-858.49 h60
M14 Component Bodies Bottom:
  text ".Layer_Name" at 577,-858.49 h60
M15 Courtyards Top:
  text ".Layer_Name" at 577,-858.49 h60
M16 Courtyards Bottom:
  text ".Layer_Name" at 577,-858.49 h60
Drill Drawing:
  circle w10: c3970.62,1445.83 r33.33
  lines w10: 3937.29,995.83 3970.62,962.5 4003.96,995.83 3970.62,1029.17 3937.29,995.83 ; 3937.29,1112.5 4003.96,1112.5 4003.96,1179.17 3937.29,1179.17 3937.29,1112.5 ; 3937.29,1262.5 3970.62,1279.17 4003.96,1262.5 3987.29,1295.83 4003.96,1329.17 3970.62,1312.5 3937.29,1329.17 3953.96,1295.83 3937.29,1262.5 ; 3937.29,1629.17 4003.96,1629.17 3970.62,1562.5 3937.29,1629.17 ; 3937.29,1729.17 3953.96,1729.17 3953.96,1712.5 3987.29,1712.5 3987.29,1729.17 4003.96,1729.17 4003.96,1762.5 3987.29,1762.5 3987.29,1779.17 3953.96,1779.17 3953.96,1762.5 3937.29,1762.5 3937.29,1729.17 ; 3937.29,1862.5 4003.96,1862.5 4003.96,1929.17 3937.29,1929.17 3937.29,1862.5 ; 3937.29,2029.17 3953.96,2029.17 3970.62,2012.5 3987.29,2029.17 4003.96,2029.17 3987.29,2045.83 4003.96,2062.5 3987.29,2062.5 3970.62,2079.17 3953.96,2062.5 3937.29,2062.5 3953.96,2045.83 3937.29,2029.17 ; 3937.29,2162.5 3937.29,2179.17 3953.96,2195.83 3937.29,2212.5 3937.29,2229.17 3953.96,2229.17 3970.62,2212.5 3987.29,2229.17 4003.96,2229.17 4003.96,2212.5 3987.29,2195.83 4003.96,2179.17 4003.96,2162.5 3987.29,2162.5 3970.62,2179.17 3953.96,2162.5 3937.29,2162.5 ; 3950.62,1875.83 3990.62,1875.83 3990.62,1915.83 3950.62,1915.83 3950.62,1875.83
  lines w15: 3877.5,917.5 11047.55,917.5 ; 3877.5,2267.5 11047.55,2267.5 ; 4428.38,767.5 4428.38,2417.5 ; 5028.22,767.5 5028.22,2417.5 ; 6177.88,767.5 6177.88,2417.5 ; 6683.76,767.5 6683.76,2417.5 ; 7417.56,767.5 7417.56,2417.5 ; 8917.11,767.5 8917.11,2417.5 ; 9506.96,767.5 9506.96,2417.5 ; 10252.76,767.5 10252.76,2417.5 ; 3877.5,767.5 11047.55,767.5 11047.55,2417.5 3877.5,2417.5 3877.5,767.5
  text "Symbol" at 3967.5,2312.5 h72
  text "Count" at 4473.38,2312.5 h72
  text "Hole Size" at 5073.22,2312.5 h72
  text "Plated" at 6222.88,2312.5 h72
  text "Hole Type" at 6728.76,2312.5 h72
  text "Drill Layer Pair" at 7462.56,2312.5 h72
  text "Via/Pad" at 8962.11,2312.5 h72
  text "Pad Shape" at 9551.96,2312.5 h72
  text "Template" at 10297.76,2312.5 h72
  text "4" at 4473.38,2162.5 h60
  text "40.16mil (1.020mm)" at 5073.22,2162.5 h60
  text "PTH" at 6222.88,2162.5 h60
  text "Round" at 6728.76,2162.5 h60
  text "Top Layer - Bottom Layer" at 7462.56,2162.5 h60
  text "Pad" at 8962.11,2162.5 h60
  text "(Mixed)" at 9551.96,2162.5 h60
  text "(Mixed)" at 10297.76,2162.5 h60
  text "4" at 4473.38,2012.5 h60
  text "68.00mil (1.727mm)" at 5073.22,2012.5 h60
  text "PTH" at 6222.88,2012.5 h60
  text "Round" at 6728.76,2012.5 h60
  text "Top Layer - Bottom Layer" at 7462.56,2012.5 h60
  text "Pad" at 8962.11,2012.5 h60
  text "Rounded" at 9551.96,2012.5 h60
  text "c254h173" at 10297.76,2012.5 h60
  text "4" at 4473.38,1862.5 h60
  text "125.98mil (3.200mm)" at 5073.22,1862.5 h60
  text "PTH" at 6222.88,1862.5 h60
  text "Round" at 6728.76,1862.5 h60
  text "Top Layer - Bottom Layer" at 7462.56,1862.5 h60
  text "Pad" at 8962.11,1862.5 h60
  text "Rounded" at 9551.96,1862.5 h60
  text "c800h320" at 10297.76,1862.5 h60
  text "6" at 4473.38,1712.5 h60
  text "29.53mil (0.750mm)" at 5073.22,1712.5 h60
  text "PTH" at 6222.88,1712.5 h60
  text "Round" at 6728.76,1712.5 h60
  text "Top Layer - Bottom Layer" at 7462.56,1712.5 h60
  text "Pad" at 8962.11,1712.5 h60
  text "(Mixed)" at 9551.96,1712.5 h60
  text "(Mixed)" at 10297.76,1712.5 h60
  text "9" at 4473.38,1562.5 h60
  text "43.31mil (1.100mm)" at 5073.22,1562.5 h60
  text "PTH" at 6222.88,1562.5 h60
  text "Round" at 6728.76,1562.5 h60
  text "Top Layer - Bottom Layer" at 7462.56,1562.5 h60
  text "Pad" at 8962.11,1562.5 h60
  text "(Mixed)" at 9551.96,1562.5 h60
  text "(Mixed)" at 10297.76,1562.5 h60
  text "14" at 4473.38,1412.5 h60
  text "7.87mil (0.200mm)" at 5073.22,1412.5 h60
  text "PTH" at 6222.88,1412.5 h60
  text "Round" at 6728.76,1412.5 h60
  text "Top Layer - Bottom Layer" at 7462.56,1412.5 h60
  text "Via" at 8962.11,1412.5 h60
  text "Rounded" at 9551.96,1412.5 h60
  text "v50h20" at 10297.76,1412.5 h60
  text "16" at 4473.38,1262.5 h60
  text "38.00mil (0.965mm)" at 5073.22,1262.5 h60
  text "PTH" at 6222.88,1262.5 h60
  text "Round" at 6728.76,1262.5 h60
  text "Top Layer - Bottom Layer" at 7462.56,1262.5 h60
  text "Pad" at 8962.11,1262.5 h60
  text "Rounded" at 9551.96,1262.5 h60
  text "c152h97" at 10297.76,1262.5 h60
  text "73" at 4473.38,1112.5 h60
  text "40.00mil (1.016mm)" at 5073.22,1112.5 h60
  text "PTH" at 6222.88,1112.5 h60
  text "Round" at 6728.76,1112.5 h60
  text "Top Layer - Bottom Layer" at 7462.56,1112.5 h60
  text "Pad" at 8962.11,1112.5 h60
  text "(Mixed)" at 9551.96,1112.5 h60
  text "(Mixed)" at 10297.76,1112.5 h60
  text "573" at 4473.38,962.5 h60
  text "10.00mil (0.254mm)" at 5073.22,962.5 h60
  text "PTH" at 6222.88,962.5 h60
  text "Round" at 6728.76,962.5 h60
  text "Top Layer - Bottom Layer" at 7462.56,962.5 h60
  text "Via" at 8962.11,962.5 h60
  text "Rounded" at 9551.96,962.5 h60
  text "v56h25m0mx0" at 10297.76,962.5 h60
  text "703 Total" at 4473.38,812.5 h60
  text ".Layer_Name" at 577,-858.49 h60
M17 Embedded Cavity:
  text ".Layer_Name" at 577,-858.49 h60
M18 Embedded Assembly:
  text ".Layer_Name" at 577,-858.49 h60
M19 Embedded Keepout:
  text ".Layer_Name" at 577,-858.49 h60

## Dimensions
0,-400 to 1000,-400 on M2 Board Dimensions
0,0 to 3500,0 on M2 Board Dimensions
0,0 to 0,3300 on M2 Board Dimensions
